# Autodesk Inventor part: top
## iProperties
Created: 2008-04
Part Number: top
Document SubType Name: Modeling
Designer: Jayson Martinez
Density: 1 g/cm^3
Author: Jayson Martinez
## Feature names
1. Extrusion1
